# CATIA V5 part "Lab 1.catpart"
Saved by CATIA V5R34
Part number: Part1
Bounding box of the stored display mesh (mm): x -70 to 70, y -50 to 50, z -10 to 33
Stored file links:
  D:\Artur\Systemy CAM\2025-2026\Dzienne\Machanika i budowa maszyn\Lab 1.catpart
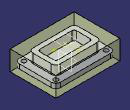
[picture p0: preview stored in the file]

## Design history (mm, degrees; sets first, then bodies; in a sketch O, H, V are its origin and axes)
Set1 "Polfabrykat"
  Sketch1 on {plane stored without definition}, origin (0, 0, -10), H (1, 0, 0), V (0, 1, 0)
    line L1 (-70, -50) -> (70, -50)
    line L2 (70, -50) -> (70, 50)
    line L3 (70, 50) -> (-70, 50)
    line L4 (-70, 50) -> (-70, -50)
  Join1: Elements ({fill Boundary Sketch1}; {fill Boundary {translate ToTransfor Sketch1, Distance 43}}; {loft Sections (Sketch1; {translate ToTransfor Sketch1, Distance 43})})
  Sketch2 on face of Join1, origin (0, 0, 33), H (1, 0, 0), V (0, 1, 0)
    point P1 (-7.0599, 15.8377)
    point P2 (0, 0)
    coincidence: P2 O
Body1 "Kostka" (main body)
  Sketch3 on xy-plane, origin (0, 0, 0), H (1, 0, 0), V (0, 1, 0)
    line L1 (65, 45) -> (65, -45)
    line L2 (65, -45) -> (-65, -45)
    line L3 (-65, -45) -> (-65, 45)
    line L4 (-65, 45) -> (65, 45)
    line L5 (50, 30) -> (50, -30)
    line L6 (50, -30) -> (-50, -30)
    line L7 (-50, -30) -> (-50, 30)
    line L8 (-50, 30) -> (50, 30)
    line L9 (40, 20) -> (40, -20)
    line L10 (40, -20) -> (-40, -20)
    line L11 (-40, -20) -> (-40, 20)
    line L12 (-40, 20) -> (40, 20)
    distance L2 L4 = 90
    distance L1 L3 = 130
    distance L8 L6 = 60
    distance L5 L7 = 100
    distance L12 L10 = 40
    distance L9 L11 = 80
    vertical: L1 V, L3 V, L5 V, L7 V, L9 V, L11 V
    horizontal: L2 H, L4 H, L6 H, L8 H, L10 H, L12 H
    equidistance: L1 L3 O, L2 L4 O, L5 L7 O, L6 L8 O, L9 L11 O, L10 L12 O
  MultiPad1: profile Sketch3, domains (length 10; length 30; length 10)
  Fillet1: radius 10, on edge [face of MultiPad1 from Sketch3.L1 | face of MultiPad1 from Sketch3.L2]; edge [face of MultiPad1 from Sketch3.L5 | face of MultiPad1 from Sketch3.L6]; edge [face of MultiPad1 from Sketch3.L4 | face of MultiPad1 from Sketch3.L1]; edge [face of MultiPad1 from Sketch3.L8 | face of MultiPad1 from Sketch3.L5]; edge [face of MultiPad1 from Sketch3.L2 | face of MultiPad1 from Sketch3.L3]; edge [face of MultiPad1 from Sketch3.L6 | face of MultiPad1 from Sketch3.L7]; edge [face of MultiPad1 from Sketch3.L7 | face of MultiPad1 from Sketch3.L8]; edge [face of MultiPad1 from Sketch3.L3 | face of MultiPad1 from Sketch3.L4]
  Fillet2: radius 5, on edge [face of MultiPad1 from Sketch3.L11 | face of MultiPad1 from Sketch3.L10]; edge [face of MultiPad1 from Sketch3.L9 | face of MultiPad1 from Sketch3.L12]; edge [face of MultiPad1 from Sketch3.L10 | face of MultiPad1 from Sketch3.L9]; edge [face of MultiPad1 from Sketch3.L12 | face of MultiPad1 from Sketch3.L11]
  Sketch4 on face of MultiPad1, origin (-42.0822, 38.8603, 10), H (1, 0, 0), V (0, 1, 0)
    point P1 (-12.9178, -3.8603)
    reference intersected line E1 through (42.0822, 0) direction (0, 1) from yz-plane
    reference intersected line E2 through (0, -38.8603) direction (-1, 0) from zx-plane
    distance P1 E1 = 55
    distance E2 P1 = 35
  Hole1: placed by Sketch4, at (-55, 35, 10) direction (0, 0, -1), diameter 10, through (limit type 6)
  RectPattern1: of Hole1, direction 1 instances 2, spacing 110, along edge [face of MultiPad1 from Sketch3.L4 | face of MultiPad1] reversed, direction 2 instances 2, spacing 70, along edge [face of MultiPad1 from Sketch3.L3 | face of MultiPad1]
  Plane1: type Offset, RefPlane face of MultiPad1, Offset 10, reversed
